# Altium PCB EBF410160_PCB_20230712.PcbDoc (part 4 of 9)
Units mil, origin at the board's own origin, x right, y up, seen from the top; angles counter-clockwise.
Board outline 5393.69 x 3858.26 mil, 6 copper layers (TOP, GND02, ART03, POW04, GND05, BOTTOM), stack 47.2 mil thick; 572 components, 434 nets, 2057 pads, 1177 vias.
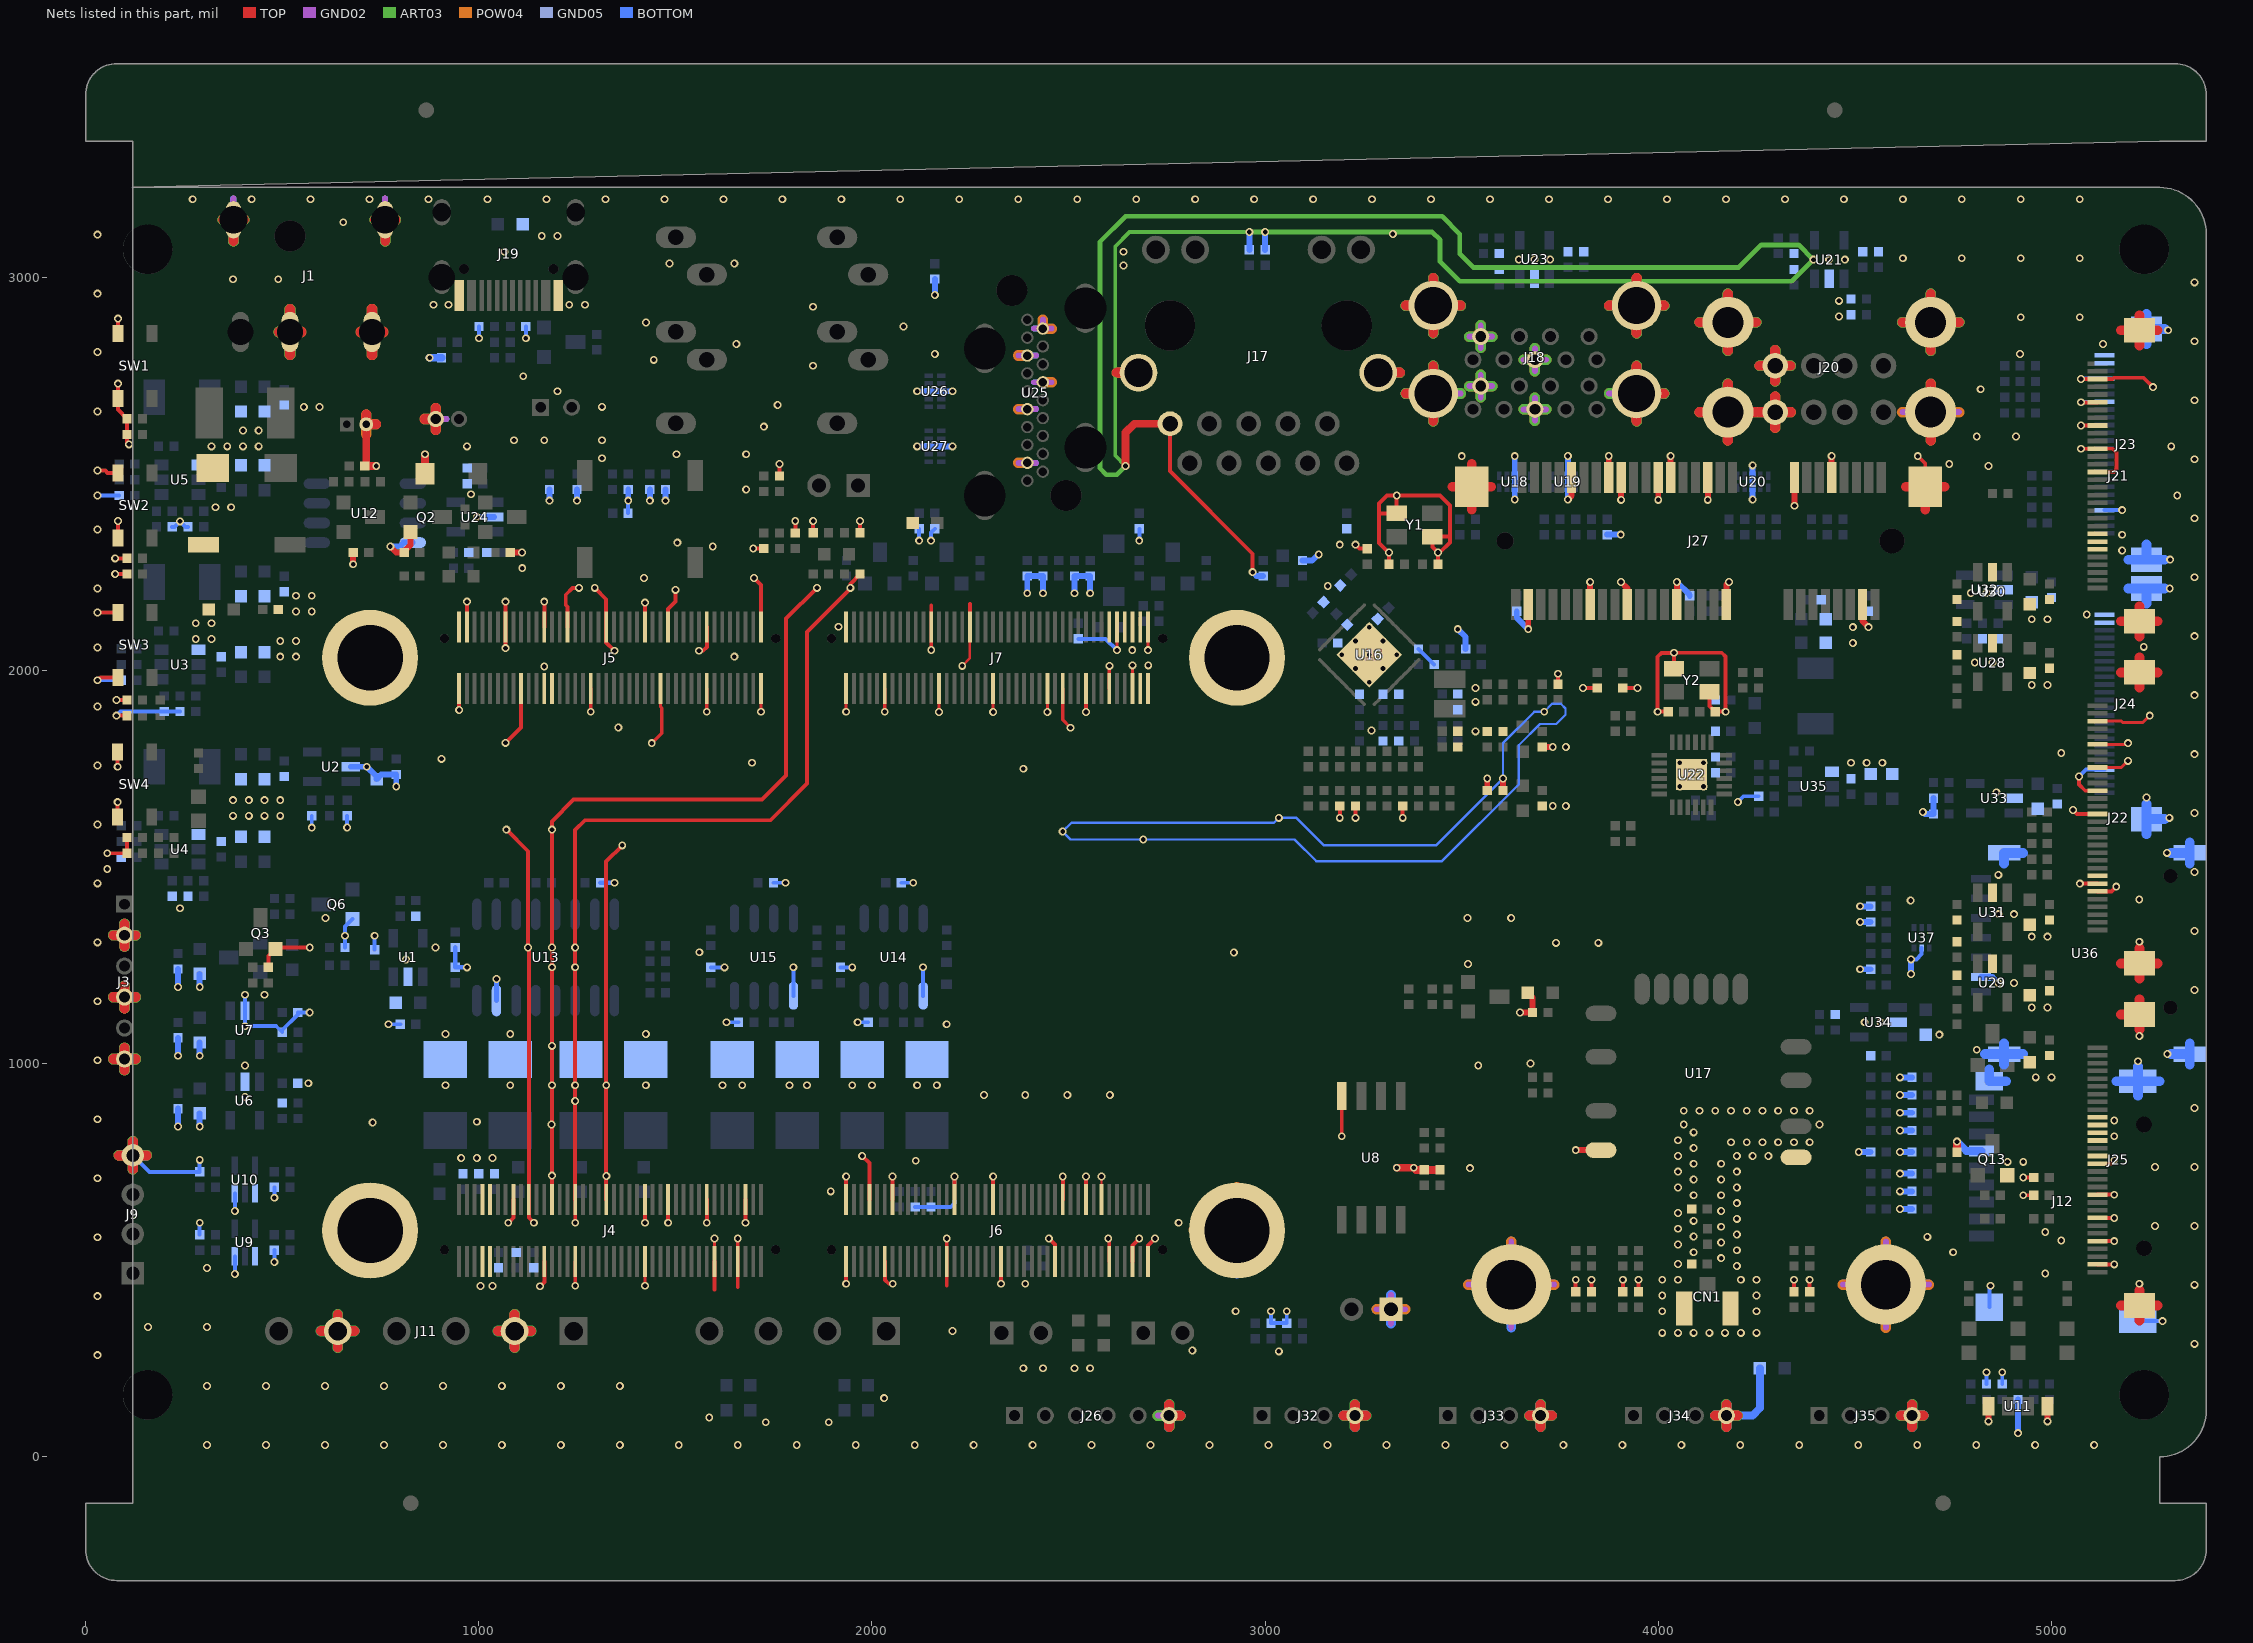
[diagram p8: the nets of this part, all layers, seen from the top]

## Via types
v1: diameter 20, hole 12, TOP to BOTTOM, 1177 vias

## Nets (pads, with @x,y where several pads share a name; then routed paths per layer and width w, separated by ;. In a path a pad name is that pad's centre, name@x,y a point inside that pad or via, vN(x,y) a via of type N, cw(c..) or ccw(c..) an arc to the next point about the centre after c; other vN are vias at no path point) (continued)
GND: C1.2 C2.2 C3.2 C4.2 C5.2 C6.2 C9.2 C10.2 C11.2 C12.2 C13.2 C14.2 C15.2 C16.2 C17.2 C18.1 C21.2 C22.2 C23.2 C24.2 C25.2 C26.2 C27.1 C30.2 C31.2 C32.2 C33.2 C34.2 C35.2 C36.2 C37.1 C39.2 C40.2 C41.2 C42.2 C43.2 C44.2 C45.2 C46.2 C47.2 C48.2 C49.2 C50.2 C51.2 C52.2 C53.2 C54.2 C55.2 C56.2 C57.2 C58.2 C59.2 C60.2 C61.2 C62.2 C63.2 C64.2 C65.2 C66.2 C67.2 C68.2 C71.2 C72.2 C73.2 C74.2 C75.2 C77.2 C78.2 C79.2 C80.2 C81.2 C82.2 C83.2 C84.2 C85.2 C86.2 C87.2 C88.2 C89.2 C90.2 C91.2 C92.2 C93.2 C94.2 C95.2 C96.2 C97.2 C98.2 C99.2 C100.2 C101.2 C102.2 C103.2 C105.2 C106.2 C108.2 C109.2 C110.2 C111.2 C114.2 C115.2 C116.2 C117.2 C118.1 C119.2 C120.2 C121.2 C122.2 C123.2 C124.2 C125.2 C126.2 C127.2 C128.2 C129.2 C130.2 C131.2 C132.2 C133.2 C134.2 C135.2 C136.2 C137.2 C138.2 C139.2 C140.2 C141.2 C142.2 C143.2 C144.2 C145.2 C148.2 C149.2 C150.2 C152.2 C153.2 C156.2 C157.2 C158.2 C159.2 C160.2 C161.2 C162.2 C163.2 C164.2 C167.2 C168.2 C169.2 C170.2 C171.2 C172.2 C173.2 C177.2 CN1.2 CN1.3 D1.2 D2.2 D3.1 D4.1 D5.1 D6.1 D7.1 D8.1 D10.1 D11.1 D12.1 D13.1 D14.1 D15.1 D16.1 D17.1 D18.1 D19.1 D20.1 D21.1 D24.1 D25.1 D26.1 D27.1 D30.1 D31.1 D33.1 D34.1 D35.1 D36.1 D37.1 D38.1 D39.1 D41.1 D42.1 D43.1 D44.1 D45.1 D46.1 D47.1 D48.1 D49.1 D50.1 D51.1 D52.1 D53.1 D54.1 J1.1 J1.2 J1.3 J1.5 J2.2 J3.2 J3.4 J3.6 J4.7 J4.8 J4.9 J4.10 J4.16 J4.20 J4.23 J4.26 J4.31 J4.32 J4.40 J4.49 J4.50 J4.56 J4.66 J4.67 J4.73 J4.76 J5.1 J5.2 J5.3 J5.13 J5.18 J5.23 J5.24 J5.26 J5.29 J5.36 J5.39 J5.49 J5.54 J5.55 J5.65 J5.66 J5.79 J5.80 J6.1 J6.2 J6.8 J6.11 J6.14 J6.27 J6.30 J6.40 J6.41 J6.55 J6.58 J6.64 J6.68 J6.69 J6.75 J6.79 J7.1 J7.2 J7.12 J7.23 J7.26 J7.33 J7.40 J7.54 J7.58 J7.64 J7.69 J7.70 J7.71 J7.73 J7.75 J7.76 J7.77 J7.78 J7.79 J7.80 J8.1 J9.4 J10.2 J11.2 J11.5 J12.6 J12.10 J12.11 J12.12 J12.13 J17.10 J17.15 J17.16 J18.4 J18.7 J18.13 J18.16 J18.19 J18.20 J18.21 J18.22 J19.A1 J19.A12 J19.B1 J19.B12 J20.4 J20.5 J20.6 J20.10 J20.11 J20.12 J21.6 J21.7 J21.8 J21.16 J21.19 J21.22 J21.25 J21.28 J21.31 J21.32 J22.6 J22.7 J22.8 J22.16 J22.19 J22.22 J22.25 J22.28 J22.31 J22.32 J23.4 J23.18 J23.21 J23.23 J23.24 J23.25 J23.26 J24.4 J24.23 J24.24 J24.25 J24.26 J25.2 J25.5 J25.8 J25.11 J25.15 J25.16 J25.18 J25.19 J25.20 J25.21 J25.31 J25.32 J26.6 J27.4 J27.9 J27.15 J27.18 J27.21 J27.26 J27.27 J27.29 J27.34 J27.35 J27.37 J27.40 J27.43 J27.50 J27.53 J27.54 J32.4 J33.4 J34.4 J35.4 L8.2 L9.2 Q2.2 Q3.2 Q6.2 Q13.2 R2.2 R5.2 R6.2 R8.2 R13.2 R15.2 R18.2 R21.2 R22.2 R25.2 R29.2 R31.2 R33.2 R35.2 R75.2 R76.2 R77.2 R78.2 R98.2 R103.2 R104.2 R105.2 R113.2 R114.2 R115.2 R116.2 R121.1 R143.2 R147.2 R150.2 R152.2 R154.2 R172.2 R173.2 R174.2 R175.2 R181.2 R187.2 R191.1 R194.2 R197.2 R203.2 R216.2 R217.2 R218.2 SS1.1 SS2.1 SS3.1 SS4.1 SS5.1 SS6.1 SW1.1 SW1.2 SW2.1 SW2.2 SW3.1 SW3.2 SW4.1 SW4.2 U1.2 U2.2 U3.1 U4.1 U5.1 U6.2 U7.2 U8.4 U9.1 U9.3 U10.1 U10.3 U11.1 U11.4 U12.4 U13.15 U14.5 U15.5 U16.41 U17.1 U17.5 U18.3 U18.8 U19.3 U19.8 U20.3 U20.8 U21.2 U22.25 U23.2 U24.2 U25.2 U25.5 U25.8 U25.11 U25.17 U26.3 U26.8 U27.3 U27.8 U28.2 U29.2 U30.2 U31.2 U32.2 U33.2 U34.2 U35.1 U36.5 U36.8 U36.9 U36.10 U36.11 U37.2 Y1.2 Y1.4 Y2.2 Y2.4 | length 67824.3
  TOP w6.16: v1(2229.53,2011.61) 2249.21,2031.3 J7.33@2249.21,2110.98 ; J6.68@2583.86,654.29 v1(2583.86,712.79)
  TOP w8: v1(1245.27,435) J4.31@1245.27,496.81 ; v1(1422.43,435) J4.49@1422.43,496.81 ; v1(1440,1815) 1465.28,1840.28 1465.28,1904.72 1461.8,1908.2 J5.54@1461.8,1953.5 ; v1(1579.91,1895) J5.66@1579.91,1953.5 ; J4.67@1599.6,496.81 v1(1599.6,555) ; J4.73@1658.65,496.81 v1(1658.65,555) ; v1(1717.71,1895) J5.80@1717.71,1953.5 ; v1(1934.25,1895) J7.2@1934.25,1953.5 ; v1(2032.68,1895) J7.12@2032.68,1953.5 ; v1(2150.79,2052) J7.23@2150.79,2110.98 ; v1(2170.47,1894.13) J7.26@2170.47,1953.5 ; v1(2308.27,1894.13) J7.40@2308.27,1953.5 ; v1(2446.06,1894.13) J7.54@2446.06,1953.5 ; J7.58@2485.43,1953.5 2485.43,1902.73 2485.12,1902.42 2485.12,1874.13 v1(2505.12,1854.13) ; v1(2623.23,2051.61) J7.71@2623.23,2110.98 ; J7.76@2662.6,1953.5 v1(2662.6,2012.87) ; v1(2701.97,2051.61) J7.79@2701.97,2110.98 ; J22.22@5117.47,1752.96 5177.96,1752.96 v1(5195,1770) ; J22.25@5117.47,1812.01 5192.01,1812.01 v1(5195,1815) ; J22.28@5117.47,1871.07 5177.65,1871.07 5181.12,1867.59 5232.59,1867.59 v1(5250,1885)
  TOP w10: v1(30,1975) 37.03,1982.03 SW3.1@82,1982.03 ; v1(30,2147.39) SW3.2@82,2147.39 ; v1(30,2508.34) 50,2508.34 55.95,2502.39 58.2,2502.39 ; v1(55,1535) C61.2@105.32,1535 D8.1@105.32,1575 ; 58.22,2502.37 SW2.2@82,2502.41 ; v1(75,2245) C58.2@105.32,2245 ; v1(75,2285) D4.1@105.32,2285 ; v1(78.52,1885) C60.2@105.32,1885 ; v1(78.52,1925) D7.1@105.32,1925 ; SW4.1@81.38,1627.59 v1(81.38,1665) ; v1(81.38,1755) SW4.2@81.38,1792.95 ; SW2.1@82,2337.05 v1(82,2380) ; v1(82,2729.42) SW1.1@82,2691.99 82,2663.32 D3.1@105.32,2640 C56.2@105.32,2600 105.32,2579.68 v1(110,2575) ; SW1.2@82,2857.35 v1(82,2894.78) ; R21.2@464.68,1245 464.68,1273.18 Q3.2@482.5,1291 486.5,1295 v1(570,1295) ; v1(949.99,1899.13) J5.2@949.99,1953.5 ; J5.3@969.68,2110.98 v1(969.68,2175) ; v1(1068.1,1815.7) 1107.47,1855.07 J5.18@1107.47,1953.5 ; v1(1068.1,2056.61) J5.13@1068.1,2110.98 v1(1068.1,2175) ; v1(1070,1595) 1125,1540 v1(1125,1295) 1127.16,1292.84 J4.20@1127.16,654.29 1127.16,607.84 v1(1140,595) ; v1(1075,595) 1087.79,607.79 J4.16@1087.79,654.29 ; v1(1155.89,433.62) 1166.53,444.26 J4.23@1166.53,496.81 ; J5.23@1166.53,2110.98 v1(1166.53,2175) ; J4.26@1186.21,654.29 v1(1186.21,715) v1(1186.21,945) v1(1186.21,1045) v1(1186.21,1245) v1(1186.21,1295) v1(1186.21,1595) 1186.21,1616.21 1241.32,1671.32 1720.16,1671.32 1781.56,1732.72 1781.56,2131.56 v1(1860,2210) ; J5.29@1225.58,2110.98 1225.58,2161.87 1221.11,2166.34 1221.11,2192.4 1238.71,2210 v1(1255,2210) ; v1(1245.27,595) J4.32@1245.27,654.29 1245,654.56 v1(1245,905) v1(1245,944.95) v1(1245,944.95) v1(1244.95,1245) v1(1244.95,1295) 1244.95,1593.79 1270.08,1618.92 1741.87,1618.92 1835,1712.06 1835,2098.2 1945,2208.2 v1(1945,2210) 1945,2220.32 R217.2@1969.68,2245 ; v1(1284.64,1895) J5.36@1284.64,1953.5 ; v1(1295,2210) 1324.01,2180.99 J5.39@1324.01,2110.98 1324.01,2070.82 1344.83,2050 v1(1345,2050) ; J4.40@1324.01,654.29 v1@1324.01,714.01 ; v1(1324.32,714.01) v1@1324.01,714.01 ; v1(1365,1555) 1324.01,1514.01 v1@1324.01,714.01 ; v1(1422.43,595) J4.50@1422.43,654.29 ; J5.49@1422.43,2110.98 v1(1422.43,2172.43) ; v1(1481.49,595) J4.56@1481.49,654.29 ; J5.55@1481.49,2110.98 1481.49,2156.49 1500,2175 v1(1500,2205) ; v1(1560,2050) 1569.91,2050 1579.91,2060 J5.65@1579.91,2110.98 ; v1(1579.91,595) J4.66@1579.91,654.29 ; 1599.6,425.4 J4.67@1599.6,496.81 ; 1658.65,431.35 J4.73@1658.65,496.81 ; v1(1678.34,595) J4.76@1678.34,654.29 ; v1(1698.2,2310.32) C172.2@1725,2310.32 ; v1(1700,2235) 1717.71,2217.29 J5.79@1717.71,2110.98 ; C177.2@1765,2494.68 v1(1765,2525) ; C171.2@1805,2349.68 v1(1805,2380) ; D41.1@1850.32,2350 v1(1850.32,2380.32) ; v1(1934.25,440) J6.1@1934.25,496.81 ; J6.2@1934.25,654.29 v1(1934.25,713) ; D44.1@1969.68,2350 v1(1969.68,2380) ; v1(1975,765) 1993.31,746.69 J6.8@1993.31,654.29 ; J6.11@2032.68,496.81 2032.68,450 2042.68,440 v1(2052.99,440) ; J6.14@2052.36,654.29 v1(2052.36,712.79) ; J7.23@2150.79,2110.98 2150.79,2164.94 ; 2190.16,434.84 J6.27@2190.16,496.81 v1(2190.16,555.31) ; J6.30@2209.84,654.29 v1(2209.84,712.79) ; J7.33@2249.21,2110.98 2249.21,2168.76 ; J6.40@2308.27,654.29 v1(2308.27,712.79) ; v1(2327.95,440) J6.41@2327.95,496.81 ; v1(2450,555) 2465.75,539.25 J6.55@2465.75,496.81 ; J6.58@2485.43,654.29 v1(2485.43,712.79) ; J6.64@2544.49,654.29 v1(2544.49,712.79) ; v1(2544.49,1894.13) J7.64@2544.49,1953.5 ; v1(2600.92,555) 2603.54,552.38 J6.69@2603.54,496.81 ; J7.70@2603.54,1953.5 2603.54,2010.98 v1(2604.17,2011.61) ; J6.75@2662.6,496.81 2662.6,537.6 v1(2680,555) ; J6.79@2701.97,496.81 2701.97,536.97 v1(2720,555) ; J17.10@2758.13,2627.52 2758.13,2506.87 2968.2,2296.8 v1(2968.2,2250) ; v1(3190,1625) R104.2@3190,1655.32 ; v1(3195,815) U8.4@3195,917.48 ; v1(3230,1625) R103.2@3230,1655.32 ; v1(3230,2320) 3240.32,2309.68 R98.2@3260,2309.68 ; C81.2@3315.32,2270 v1(3315.32,2300) 3314.36,2300 3290,2324.36 3290,2399 ; v1(3350,1625) R105.2@3350,1655.32 ; C82.2@3439.68,2270 v1(3439.68,2300) ; R113.2@3745,1964.68 v1(3745,1991.48) ; D48.1@3790,419.68 v1(3790,450) ; v1(3808.66,1955.32) D39.1@3845,1955.32 ; D47.1@3830,419.68 v1(3830,450) ; D52.1@3910,419.68 v1(3910,450) ; D38.1@3910,1955.32 v1(3947.03,1955.32) ; D51.1@3950,419.68 v1(3950,450) ; C118.1@4025.32,1895 v1(3998.52,1895) 3998.52,2034.72 4008.52,2044.72 v1@4039.72,2044.72 ; Y2.2@4039.72,2004.53 v1@4039.72,2044.72 ; Y2.4@4130.28,1945.47 4130.28,1909.4 C117.2@4144.68,1895 v1(4171.48,1895) 4171.48,2035 4161.48,2045 v1(4040,2045) v1@4039.72,2044.72 ; D54.1@4345,419.68 v1(4345,450) ; D53.1@4385,419.68 v1(4385,450) ; v1(4660,2545) 4679.19,2525.81 J27.54@4679.19,2467.26 ; v1(4928.52,665) R191.1@4955.32,665 ; v1(4928.52,710) C150.2@4955.32,710 ; v1(5055,1645) 5065.15,1634.85 J22.16@5117.47,1634.85 ; v1(5070,1730) 5070,1710 5086.1,1693.9 J22.19@5117.47,1693.9 ; v1(5072.32,1457.68) J22.7@5117.47,1457.68 ; v1(5075,2563.9) J21.19@5117.47,2563.9 5155.92,2563.9 5165.92,2553.9 5165.92,2511.92 5158.85,2504.85 J21.16@5117.47,2504.85 ; v1(5075,2622.96) J21.22@5117.47,2622.96 ; v1(5075,2682.01) J21.25@5117.47,2682.01 ; v1(5075,2741.07) J21.28@5117.47,2741.07 5156.07,2741.07 5159.38,2744.38 5234.64,2744.38 v1(5258.5,2720.52) ; J25.2@5117.47,489.26 v1(5160,489.26) ; J25.5@5117.47,548.31 v1(5160,548.31) ; J25.8@5117.47,607.37 v1(5160,607.37) ; J25.11@5117.47,666.42 v1(5160,666.42) ; J25.15@5117.47,745.16 5151.16,745.16 v1(5160,754) ; J22.6@5117.47,1438 5153,1438 v1(5165,1450) ; 3290,2399 3290,2425 3310,2445 v1(3334.72,2445) ; 3290,2399 3290.53,2399.53 Y1.4@3334.72,2399.53 v1(3334.72,2445) ; v1(3334.72,2445) 3445,2445 3470,2420 3470,2340 ; v1(3439.68,2300) 3425.28,2314.4 Y1.2@3425.28,2340.47 3469.53,2340.47 3470,2340 ; v1(3439.68,2300) 3444.22,2300 3470,2325.78 3470,2340
  TOP w15: v1(680.32,2270) C65.2@680.32,2300 ; v1(775,2315) 790,2300 R18.2@810.32,2300 810.32,2303.33 826.5,2319.51 Q2.2@826.5,2352.5 ; C30.2@1079.68,2300 v1(1110,2300) ; C102.2@3565,1694.68 v1(3565,1725) ; C101.2@3605,1694.68 v1(3605,1725) ; v1(3648.52,1130) C109.2@3680.32,1130 3680.32,1168.18 C108.2@3668.5,1180 ; v1(3669.34,2105) J27.50@3669.34,2168.04 ; C88.2@3705,1805.32 v1(3731.8,1805.32) ; v1(3770,2435) 3779.58,2444.58 J27.43@3779.58,2490.88 ; v1(3790,779.84) U17.5@3854.39,779.84 ; J27.40@3826.82,2168.04 v1(3826.82,2225) ; J27.37@3874.07,2490.88 v1(3874.07,2545.25) ; v1(3905,2225) 3921.31,2208.69 J27.34@3921.31,2168.04 ; v1(3905.57,2433.92) J27.35@3905.57,2490.88 ; v1(4000.05,2433.92) J27.29@4000.05,2490.88 ; J27.27@4031.55,2490.88 v1(4031.55,2545.25) ; J27.26@4047.3,2168.04 v1(4047.3,2225) ; v1(4126.04,2433.92) J27.21@4126.04,2490.88 ; J27.18@4173.28,2168.04 4173.28,2218.28 v1(4180,2225) ; v1(4346.51,2418.78) J27.15@4346.51,2490.88 ; J27.9@4441,2490.88 v1(4441,2545.25) ; J27.4@4519.74,2168.04 4519.74,2125.26 v1(4535,2110) ; v1(4840,90) U11.1@4840,128.74 ; v1(4990,90) U11.4@4990,128.74
  TOP w20: J10.2@713.59,2625.98 713.59,2523.91 D10.1@709.68,2520 v1(739,2520) ; D2.2@863.07,2500 v1(863.07,2550) ; v1(2645,2520) 2645,2605 2667.52,2627.52 J17.10@2758.13,2627.52 ; v1(3335,735) v1(3378.2,735) 3383.52,729.68 C55.2@3405,729.68 C54.2@3445,729.68 ; R197.2@4760,774.68 v1(4760,801.48)
  TOP w25: 70.08,1011.58 J3.6@98.74,1011.58 ; 70.08,1169.06 J3.4@98.74,1169.06 ; 70.08,1326.54 J3.2@98.74,1326.54 ; 84.45,766.54 J9.4@120,766.54 ; 98.74,982.92 J3.6@98.74,1011.58 ; 98.74,1040.23 J3.6@98.74,1011.58 ; 98.74,1140.4 J3.4@98.74,1169.06 ; 98.74,1197.71 J3.4@98.74,1169.06 ; 98.74,1297.88 J3.2@98.74,1326.54 ; 98.74,1355.19 J3.2@98.74,1326.54 ; 120,731 J9.4@120,766.54 ; 120,802.09 J9.4@120,766.54 ; 127.4,1011.58 J3.6@98.74,1011.58 ; 127.4,1169.06 J3.4@98.74,1169.06 ; 127.4,1326.54 J3.2@98.74,1326.54 ; 155.55,766.54 J9.4@120,766.54 ; 349.3,3146.28 J1.1@376,3146.28 ; 376,3092.03 J1.1@376,3146.28 ; 402.7,3146.28 J1.1@376,3146.28 ; 491.05,2860.78 J1.2@519.7,2860.78 ; 519.7,2802.57 J1.2@519.7,2860.78 ; 519.7,2918.98 J1.2@519.7,2860.78 ; 548.35,2860.78 J1.2@519.7,2860.78 ; 598.71,319.64 J11.5@641.14,319.64 ; 641.14,277.21 J11.5@641.14,319.64 ; 641.14,362.08 J11.5@641.14,319.64 ; 683.58,319.64 J11.5@641.14,319.64 ; 699.65,2860.78 J1.3@728.3,2860.78 ; 713.59,2650.7 J10.2@713.59,2625.98 738.31,2625.98 ; 728.3,2802.57 J1.3@728.3,2860.78 ; 728.3,2918.98 J1.3@728.3,2860.78 ; 735.1,3146.28 J1.5@761.8,3146.28 ; 756.96,2860.78 J1.3@728.3,2860.78 ; 761.8,3092.03 J1.5@761.8,3146.28 ; 788.51,3146.28 J1.5@761.8,3146.28 ; 862.8,2639.41 J2.2@890.47,2639.41 ; 890.47,2611.73 J2.2@890.47,2639.41 ; 890.47,2667.08 J2.2@890.47,2639.41 ; 1048.7,319.64 J11.2@1091.14,319.64 ; 1091.14,277.21 J11.2@1091.14,319.64 ; 1091.14,362.08 J11.2@1091.14,319.64 ; 1133.58,319.64 J11.2@1091.14,319.64 ; 2623.17,2757.44 J17.16@2678.01,2757.44 ; 2755.9,75.83 J26.6@2755.9,104.49 ; 2755.9,133.14 J26.6@2755.9,104.49 ; 2784.56,104.49 J26.6@2755.9,104.49 ; 3199.68,104.49 J32.4@3228.34,104.49 ; 3228.34,75.83 J32.4@3228.34,104.49 ; 3228.34,133.14 J32.4@3228.34,104.49 ; 3257,104.49 J32.4@3228.34,104.49 ; J17.15@3287.85,2757.44 3342.69,2757.44 ; 3357.63,2704.29 J18.20@3427.62,2704.29 ; 3357.63,2927.91 J18.19@3427.62,2927.91 ; 3427.62,2634.3 J18.20@3427.62,2704.29 ; 3427.62,2774.28 J18.20@3427.62,2704.29 ; 3427.62,2857.92 J18.19@3427.62,2927.91 ; 3427.62,2997.9 J18.19@3427.62,2927.91 ; 3476.32,2467.26 J27.53@3525.64,2467.26 ; 3497.61,2927.91 J18.19@3427.62,2927.91 ; 3525.64,2409.07 J27.53@3525.64,2467.26 ; 3525.64,2525.44 J27.53@3525.64,2467.26 ; 3574.97,2467.26 J27.53@3525.64,2467.26 ; 3672.12,104.49 J33.4@3700.78,104.49 ; 3700.78,75.83 J33.4@3700.78,104.49 ; 3700.78,133.14 J33.4@3700.78,104.49 ; 3729.44,104.49 J33.4@3700.78,104.49 ; 3874.96,2927.91 J18.22@3944.95,2927.91 ; 3944.95,2634.3 J18.21@3944.95,2704.29 ; 3944.95,2774.28 J18.21@3944.95,2704.29 ; 3944.95,2857.92 J18.22@3944.95,2927.91 ; 3944.95,2997.9 J18.22@3944.95,2927.91 ; 4014.94,2704.29 J18.21@3944.95,2704.29 ; 4014.94,2927.91 J18.22@3944.95,2927.91 ; 4105.27,2657.04 J20.5@4177.23,2657.04 ; 4105.27,2885.39 J20.11@4177.23,2885.39 ; 4144.56,104.49 J34.4@4173.22,104.49 ; 4173.22,75.83 J34.4@4173.22,104.49 ; 4173.22,133.14 J34.4@4173.22,104.49 ; 4177.23,2585.08 J20.5@4177.23,2657.04 ; 4177.23,2729 J20.5@4177.23,2657.04 ; 4177.23,2813.43 J20.11@4177.23,2885.39 ; 4177.23,2957.35 J20.11@4177.23,2885.39 ; 4201.88,104.49 J34.4@4173.22,104.49 ; 4249.19,2657.04 J20.5@4177.23,2657.04 ; 4249.19,2885.39 J20.11@4177.23,2885.39 ; 4257.8,2657.04 J20.4@4297.3,2657.04 ; 4257.8,2775.15 J20.10@4297.3,2775.15 ; 4297.3,2617.54 J20.4@4297.3,2657.04 ; 4297.3,2696.54 J20.4@4297.3,2657.04 ; 4297.3,2735.65 J20.10@4297.3,2775.15 ; 4297.3,2814.65 J20.10@4297.3,2775.15 ; 4336.8,2657.04 J20.4@4297.3,2657.04 ; 4336.8,2775.15 J20.10@4297.3,2775.15 ; 4617,104.49 J35.4@4645.66,104.49 ; 4621.01,2885.39 J20.12@4692.97,2885.39 ; 4629.86,2467.26 J27.54@4679.19,2467.26 ; 4645.66,75.83 J35.4@4645.66,104.49 ; 4645.66,133.14 J35.4@4645.66,104.49 ; 4674.32,104.49 J35.4@4645.66,104.49 ; 4679.19,2409.07 J27.54@4679.19,2467.26 ; 4692.97,2585.08 J20.6@4692.97,2657.04 4692.97,2729 ; 4692.97,2813.43 J20.12@4692.97,2885.39 ; 4692.97,2957.35 J20.12@4692.97,2885.39 ; 4728.51,2467.26 J27.54@4679.19,2467.26 ; 4764.93,2885.39 J20.12@4692.97,2885.39 ; 5177.4,384.92 J25.32@5223.77,384.92 ; 5177.4,1125.08 J25.31@5223.77,1125.08 ; 5177.4,1254.92 J22.32@5223.77,1254.92 ; 5177.4,1995.08 J22.31@5223.77,1995.08 ; 5177.4,2124.92 J21.32@5223.77,2124.92 ; 5177.4,2865.08 J21.31@5223.77,2865.08 ; 5223.77,346.42 J25.32@5223.77,384.92 ; 5223.77,423.41 J25.32@5223.77,384.92 ; 5223.77,1086.58 J25.31@5223.77,1125.08 ; 5223.77,1163.57 J25.31@5223.77,1125.08 ; 5223.77,1216.42 J22.32@5223.77,1254.92 ; 5223.77,1293.41 J22.32@5223.77,1254.92 ; 5223.77,1956.58 J22.31@5223.77,1995.08 ; 5223.77,2033.57 J22.31@5223.77,1995.08 ; 5223.77,2086.42 J21.32@5223.77,2124.92 ; 5223.77,2163.41 J21.32@5223.77,2124.92 ; 5223.77,2826.58 J21.31@5223.77,2865.08 ; 5223.77,2903.57 J21.31@5223.77,2865.08 ; 5270.14,384.92 J25.32@5223.77,384.92 ; 5270.14,1254.92 J22.32@5223.77,1254.92 ; 5270.14,1995.08 J22.31@5223.77,1995.08 ; 5270.14,2124.92 J21.32@5223.77,2124.92 ; 5270.14,2865.08 J21.31@5223.77,2865.08
  GND02 w15: 70.08,1011.58 J3.6@98.74,1011.58 ; 70.08,1169.06 J3.4@98.74,1169.06 ; 70.08,1326.54 J3.2@98.74,1326.54 ; 84.45,766.54 J9.4@120,766.54 ; 98.74,982.92 J3.6@98.74,1011.58 ; 98.74,1040.23 J3.6@98.74,1011.58 ; 98.74,1140.4 J3.4@98.74,1169.06 ; 98.74,1197.71 J3.4@98.74,1169.06 ; 98.74,1297.88 J3.2@98.74,1326.54 ; 98.74,1355.19 J3.2@98.74,1326.54 ; 120,731 J9.4@120,766.54 ; 120,802.09 J9.4@120,766.54 ; 127.4,1011.58 J3.6@98.74,1011.58 ; 127.4,1169.06 J3.4@98.74,1169.06 ; 127.4,1326.54 J3.2@98.74,1326.54 ; 155.55,766.54 J9.4@120,766.54 ; 349.3,3146.28 J1.1@376,3146.28 ; 376,3092.03 J1.1@376,3146.28 ; 376,3200.53 J1.1@376,3146.28 ; 402.7,3146.28 J1.1@376,3146.28 ; 491.05,2860.78 J1.2@519.7,2860.78 ; 519.7,2802.57 J1.2@519.7,2860.78 ; 519.7,2918.98 J1.2@519.7,2860.78 ; 548.35,2860.78 J1.2@519.7,2860.78 ; 598.71,319.64 J11.5@641.14,319.64 ; 614.26,575.55 SS1.1@723.62,575.55 ; 614.26,2032.24 SS3.1@723.62,2032.24 ; 641.14,277.21 J11.5@641.14,319.64 ; 641.14,362.08 J11.5@641.14,319.64 ; 683.58,319.64 J11.5@641.14,319.64 ; 699.65,2860.78 J1.3@728.3,2860.78 ; 713.59,2601.26 J10.2@713.59,2625.98 ; 713.59,2650.7 J10.2@713.59,2625.98 ; 723.62,466.19 SS1.1@723.62,575.55 ; 723.62,684.91 SS1.1@723.62,575.55 ; 723.62,1922.88 SS3.1@723.62,2032.24 ; 723.62,2141.6 SS3.1@723.62,2032.24 ; 728.3,2802.57 J1.3@728.3,2860.78 ; 728.3,2918.98 J1.3@728.3,2860.78 ; 735.1,3146.28 J1.5@761.8,3146.28 ; 738.31,2625.98 J10.2@713.59,2625.98 ; 756.96,2860.78 J1.3@728.3,2860.78 ; 761.8,3092.03 J1.5@761.8,3146.28 ; 761.8,3200.53 J1.5@761.8,3146.28 ; 788.51,3146.28 J1.5@761.8,3146.28 ; 832.98,575.55 SS1.1@723.62,575.55 ; 832.98,2032.24 SS3.1@723.62,2032.24 ; 862.8,2639.41 J2.2@890.47,2639.41 ; 890.47,2611.73 J2.2@890.47,2639.41 ; 890.47,2667.08 J2.2@890.47,2639.41 ; 918.14,2639.41 J2.2@890.47,2639.41 ; 1048.7,319.64 J11.2@1091.14,319.64 ; 1091.14,277.21 J11.2@1091.14,319.64 ; 1091.14,362.08 J11.2@1091.14,319.64 ; 1133.58,319.64 J11.2@1091.14,319.64 ; 2372.42,2528.08 U25.17@2395.17,2528.08 2417.92,2528.08 ; 2372.42,2664.49 U25.11@2395.17,2664.49 2417.92,2664.49 ; 2372.42,2800.91 U25.5@2395.17,2800.91 2417.92,2800.91 ; 2411.79,2732.92 U25.8@2434.54,2732.92 2457.29,2732.92 ; 2411.79,2869.46 U25.2@2434.54,2869.46 ; 2434.54,2892.21 U25.2@2434.54,2869.46 ; 2457.29,2869.46 U25.2@2434.54,2869.46 ; 2727.24,104.49 J26.6@2755.9,104.49 ; 2755.9,75.83 J26.6@2755.9,104.49 ; 2755.9,133.14 J26.6@2755.9,104.49 ; 2784.56,104.49 J26.6@2755.9,104.49 ; 2818.98,575.55 SS2.1@2928.34,575.55 ; 2818.98,2032.24 SS4.1@2928.34,2032.24 ; 2928.34,466.19 SS2.1@2928.34,575.55 ; 2928.34,684.91 SS2.1@2928.34,575.55 ; 2928.34,1922.88 SS4.1@2928.34,2032.24 ; 2928.34,2141.6 SS4.1@2928.34,2032.24 ; 3037.7,575.55 SS2.1@2928.34,575.55 ; 3037.7,2032.24 SS4.1@2928.34,2032.24 ; 3199.68,104.49 J32.4@3228.34,104.49 ; 3228.34,75.83 J32.4@3228.34,104.49 ; 3228.34,133.14 J32.4@3228.34,104.49 ; 3257,104.49 J32.4@3228.34,104.49 ; 3283.47,375 J8.1@3320,375 ; 3320,338.47 J8.1@3320,375 ; 3320,411.53 J8.1@3320,375 ; 3356.53,375 J8.1@3320,375 ; 3357.63,2704.29 J18.20@3427.62,2704.29 ; 3357.63,2927.91 J18.19@3427.62,2927.91 ; 3427.62,2634.3 J18.20@3427.62,2704.29 ; 3427.62,2774.28 J18.20@3427.62,2704.29 ; 3427.62,2857.92 J18.19@3427.62,2927.91 ; 3427.62,2997.9 J18.19@3427.62,2927.91 ; 3497.61,2704.29 J18.20@3427.62,2704.29 ; 3497.61,2927.91 J18.19@3427.62,2927.91 ; 3516.67,437.78 SS5.1@3626.03,437.78 ; 3519.83,2723.19 J18.13@3548.49,2723.19 ; 3519.83,2849.17 J18.4@3548.49,2849.17 ; 3548.49,2694.53 J18.13@3548.49,2723.19 ; 3548.49,2751.85 J18.13@3548.49,2723.19 ; 3548.49,2820.51 J18.4@3548.49,2849.17 ; 3548.49,2877.83 J18.4@3548.49,2849.17 ; 3577.15,2723.19 J18.13@3548.49,2723.19 ; 3577.15,2849.17 J18.4@3548.49,2849.17 ; 3626.03,328.42 SS5.1@3626.03,437.78 ; 3626.03,547.14 SS5.1@3626.03,437.78 ; 3657.62,2664.13 J18.16@3686.28,2664.13 ; 3657.62,2790.12 J18.7@3686.28,2790.12 ; 3672.12,104.49 J33.4@3700.78,104.49 ; 3686.28,2635.47 J18.16@3686.28,2664.13 ; 3686.28,2692.79 J18.16@3686.28,2664.13 ; 3686.28,2761.46 J18.7@3686.28,2790.12 ; 3686.28,2818.78 J18.7@3686.28,2790.12 ; 3700.78,75.83 J33.4@3700.78,104.49 ; 3700.78,133.14 J33.4@3700.78,104.49 ; 3714.94,2664.13 J18.16@3686.28,2664.13 ; 3714.94,2790.12 J18.7@3686.28,2790.12 ; 3729.44,104.49 J33.4@3700.78,104.49 ; 3735.39,437.78 SS5.1@3626.03,437.78 ; 3874.96,2704.29 J18.21@3944.95,2704.29 ; 3874.96,2927.91 J18.22@3944.95,2927.91 ; 3944.95,2634.3 J18.21@3944.95,2704.29 ; 3944.95,2774.28 J18.21@3944.95,2704.29 ; 3944.95,2857.92 J18.22@3944.95,2927.91 ; 3944.95,2997.9 J18.22@3944.95,2927.91 ; 4014.94,2704.29 J18.21@3944.95,2704.29 ; 4014.94,2927.91 J18.22@3944.95,2927.91 ; 4105.27,2657.04 J20.5@4177.23,2657.04 ; 4105.27,2885.39 J20.11@4177.23,2885.39 ; 4144.56,104.49 J34.4@4173.22,104.49 ; 4173.22,75.83 J34.4@4173.22,104.49 ; 4173.22,133.14 J34.4@4173.22,104.49 ; 4177.23,2585.08 J20.5@4177.23,2657.04 ; 4177.23,2729 J20.5@4177.23,2657.04 ; 4177.23,2813.43 J20.11@4177.23,2885.39 ; 4177.23,2957.35 J20.11@4177.23,2885.39 ; 4201.88,104.49 J34.4@4173.22,104.49 ; 4249.19,2657.04 J20.5@4177.23,2657.04 ; 4249.19,2885.39 J20.11@4177.23,2885.39 ; 4257.8,2657.04 J20.4@4297.3,2657.04 ; 4257.8,2775.15 J20.10@4297.3,2775.15 ; 4297.3,2617.54 J20.4@4297.3,2657.04 ; 4297.3,2696.54 J20.4@4297.3,2657.04 ; 4297.3,2735.65 J20.10@4297.3,2775.15 ; 4297.3,2814.65 J20.10@4297.3,2775.15 ; 4336.8,2657.04 J20.4@4297.3,2657.04 ; 4336.8,2775.15 J20.10@4297.3,2775.15 ; 4469.43,437.78 SS6.1@4578.79,437.78 ; 4578.79,328.42 SS6.1@4578.79,437.78 ; 4578.79,547.14 SS6.1@4578.79,437.78 ; 4617,104.49 J35.4@4645.66,104.49 ; 4621.01,2657.04 J20.6@4692.97,2657.04 ; 4621.01,2885.39 J20.12@4692.97,2885.39 ; 4645.66,75.83 J35.4@4645.66,104.49 ; 4645.66,133.14 J35.4@4645.66,104.49 ; 4674.32,104.49 J35.4@4645.66,104.49 ; 4688.15,437.78 SS6.1@4578.79,437.78 ; 4692.97,2585.08 J20.6@4692.97,2657.04 ; 4692.97,2729 J20.6@4692.97,2657.04 ; 4692.97,2813.43 J20.12@4692.97,2885.39 ; 4692.97,2957.35 J20.12@4692.97,2885.39 ; 4764.93,2657.04 J20.6@4692.97,2657.04 ; 4764.93,2885.39 J20.12@4692.97,2885.39
  GND02 w20: 2623.17,2757.44 J17.16@2678.01,2757.44 ; J17.15@3287.85,2757.44 3342.69,2757.44
  ART03 w10: v1(2645,2520) 2618.8,2546.2 2618.8,3078.8 2655,3115 v1(2960,3115)
  ART03 w12: v1(2645,2520) 2623,2498 2595.89,2498 2580,2513.89 2580,3090 2645,3155 3450,3155 3495,3110 3495,3059.45 3529.45,3025 4205,3025 4262.32,3082.32 4357.05,3082.32 v1(4394.61,3044.76) 4339.85,2990 3495,2990 3445,3040 3445,3095 3425,3115 v1(3000,3115) v1(2960,3115)
  ART03 w27: 70.08,1011.58 J3.6@98.74,1011.58 ; 70.08,1169.06 J3.4@98.74,1169.06 ; 70.08,1326.54 J3.2@98.74,1326.54 ; 84.45,766.54 J9.4@120,766.54 ; 98.74,982.92 J3.6@98.74,1011.58 ; 98.74,1040.23 J3.6@98.74,1011.58 ; 98.74,1140.4 J3.4@98.74,1169.06 ; 98.74,1197.71 J3.4@98.74,1169.06 ; 98.74,1297.88 J3.2@98.74,1326.54 ; 98.74,1355.19 J3.2@98.74,1326.54 ; 120,731 J9.4@120,766.54 ; 120,802.09 J9.4@120,766.54 ; 127.4,1011.58 J3.6@98.74,1011.58 ; 127.4,1169.06 J3.4@98.74,1169.06 ; 127.4,1326.54 J3.2@98.74,1326.54 ; 155.55,766.54 J9.4@120,766.54 ; 349.3,3146.28 J1.1@376,3146.28 ; 376,3092.03 J1.1@376,3146.28 ; 402.7,3146.28 J1.1@376,3146.28 ; 491.05,2860.78 J1.2@519.7,2860.78 ; 519.7,2802.57 J1.2@519.7,2860.78 ; 519.7,2918.98 J1.2@519.7,2860.78 ; 598.71,319.64 J11.5@641.14,319.64 ; 641.14,277.21 J11.5@641.14,319.64 ; 641.14,362.08 J11.5@641.14,319.64 ; 683.58,319.64 J11.5@641.14,319.64 ; 735.1,3146.28 J1.5@761.8,3146.28 ; 761.8,3092.03 J1.5@761.8,3146.28 ; 788.51,3146.28 J1.5@761.8,3146.28 ; 1048.7,319.64 J11.2@1091.14,319.64 ; 1091.14,277.21 J11.2@1091.14,319.64 ; 1091.14,362.08 J11.2@1091.14,319.64 ; 1133.58,319.64 J11.2@1091.14,319.64 ; 2727.24,104.49 J26.6@2755.9,104.49 ; 2755.9,75.83 J26.6@2755.9,104.49 ; 2755.9,133.14 J26.6@2755.9,104.49 ; 2784.56,104.49 J26.6@2755.9,104.49 ; 3199.68,104.49 J32.4@3228.34,104.49 ; 3228.34,75.83 J32.4@3228.34,104.49 ; 3228.34,133.14 J32.4@3228.34,104.49 ; 3257,104.49 J32.4@3228.34,104.49 ; J17.15@3287.85,2757.44 3342.69,2757.44 ; 3357.63,2704.29 J18.20@3427.62,2704.29 ; 3357.63,2927.91 J18.19@3427.62,2927.91 ; 3427.62,2634.3 J18.20@3427.62,2704.29 ; 3427.62,2774.28 J18.20@3427.62,2704.29 ; 3427.62,2857.92 J18.19@3427.62,2927.91 ; 3427.62,2997.9 J18.19@3427.62,2927.91 ; 3497.61,2704.29 J18.20@3427.62,2704.29 ; 3497.61,2927.91 J18.19@3427.62,2927.91 ; 3519.83,2723.19 J18.13@3548.49,2723.19 ; 3519.83,2849.17 J18.4@3548.49,2849.17 ; 3548.49,2694.53 J18.13@3548.49,2723.19 ; 3548.49,2751.85 J18.13@3548.49,2723.19 ; 3548.49,2820.51 J18.4@3548.49,2849.17 ; 3548.49,2877.83 J18.4@3548.49,2849.17 ; 3577.15,2723.19 J18.13@3548.49,2723.19 ; 3577.15,2849.17 J18.4@3548.49,2849.17 ; 3657.62,2664.13 J18.16@3686.28,2664.13 ; 3657.62,2790.12 J18.7@3686.28,2790.12 ; 3672.12,104.49 J33.4@3700.78,104.49 ; 3686.28,2635.47 J18.16@3686.28,2664.13 ; 3686.28,2692.79 J18.16@3686.28,2664.13 ; 3686.28,2761.46 J18.7@3686.28,2790.12 ; 3686.28,2818.78 J18.7@3686.28,2790.12 ; 3700.78,75.83 J33.4@3700.78,104.49 ; 3700.78,133.14 J33.4@3700.78,104.49 ; 3714.94,2664.13 J18.16@3686.28,2664.13 ; 3714.94,2790.12 J18.7@3686.28,2790.12 ; 3729.44,104.49 J33.4@3700.78,104.49 ; 3874.96,2704.29 J18.21@3944.95,2704.29 ; 3874.96,2927.91 J18.22@3944.95,2927.91 ; 3944.95,2634.3 J18.21@3944.95,2704.29 ; 3944.95,2774.28 J18.21@3944.95,2704.29 ; 3944.95,2857.92 J18.22@3944.95,2927.91 ; 4014.94,2704.29 J18.21@3944.95,2704.29 ; 4014.94,2927.91 J18.22@3944.95,2927.91 ; 4105.27,2885.39 J20.11@4177.23,2885.39 ; 4144.56,104.49 J34.4@4173.22,104.49 ; 4173.22,75.83 J34.4@4173.22,104.49 ; 4173.22,133.14 J34.4@4173.22,104.49 ; J20.5@4177.23,2657.04 4177.23,2729 ; 4177.23,2813.43 J20.11@4177.23,2885.39 ; 4177.23,2957.35 J20.11@4177.23,2885.39 ; 4201.88,104.49 J34.4@4173.22,104.49 ; 4249.19,2885.39 J20.11@4177.23,2885.39 ; 4257.8,2775.15 J20.10@4297.3,2775.15 ; 4297.3,2735.65 J20.10@4297.3,2775.15 ; 4297.3,2814.65 J20.10@4297.3,2775.15 ; 4336.8,2775.15 J20.10@4297.3,2775.15 ; 4617,104.49 J35.4@4645.66,104.49 ; 4621.01,2885.39 J20.12@4692.97,2885.39 ; 4645.66,75.83 J35.4@4645.66,104.49 ; 4645.66,133.14 J35.4@4645.66,104.49 ; 4674.32,104.49 J35.4@4645.66,104.49 ; 4692.97,2813.43 J20.12@4692.97,2885.39 ; 4692.97,2957.35 J20.12@4692.97,2885.39 ; 4764.93,2885.39 J20.12@4692.97,2885.39
  POW04 w27: 70.08,1011.58 J3.6@98.74,1011.58 ; 70.08,1169.06 J3.4@98.74,1169.06 ; 70.08,1326.54 J3.2@98.74,1326.54 ; 84.45,766.54 J9.4@120,766.54 ; 98.74,982.92 J3.6@98.74,1011.58 ; 98.74,1040.23 J3.6@98.74,1011.58 ; 98.74,1140.4 J3.4@98.74,1169.06 ; 98.74,1197.71 J3.4@98.74,1169.06 ; 98.74,1297.88 J3.2@98.74,1326.54 ; 98.74,1355.19 J3.2@98.74,1326.54 ; 120,731 J9.4@120,766.54 ; 120,802.09 J9.4@120,766.54 ; 127.4,1011.58 J3.6@98.74,1011.58 ; 127.4,1169.06 J3.4@98.74,1169.06 ; 127.4,1326.54 J3.2@98.74,1326.54 ; 155.55,766.54 J9.4@120,766.54 ; 349.3,3146.28 J1.1@376,3146.28 ; 376,3092.03 J1.1@376,3146.28 ; 402.7,3146.28 J1.1@376,3146.28 ; 491.05,2860.78 J1.2@519.7,2860.78 ; 519.7,2802.57 J1.2@519.7,2860.78 ; 519.7,2918.98 J1.2@519.7,2860.78 ; 548.35,2860.78 J1.2@519.7,2860.78 ; 699.65,2860.78 J1.3@728.3,2860.78 ; 713.59,2601.26 J10.2@713.59,2625.98 ; 713.59,2650.7 J10.2@713.59,2625.98 ; 728.3,2802.57 J1.3@728.3,2860.78 ; 728.3,2918.98 J1.3@728.3,2860.78 ; 735.1,3146.28 J1.5@761.8,3146.28 ; 738.31,2625.98 J10.2@713.59,2625.98 ; 756.96,2860.78 J1.3@728.3,2860.78 ; 761.8,3092.03 J1.5@761.8,3146.28 ; 788.51,3146.28 J1.5@761.8,3146.28 ; 862.8,2639.41 J2.2@890.47,2639.41 ; 890.47,2611.73 J2.2@890.47,2639.41 ; 890.47,2667.08 J2.2@890.47,2639.41 ; J11.2@1091.14,319.64 1091.14,362.08 ; 2372.42,2528.08 U25.17@2395.17,2528.08 ; 2372.42,2664.49 U25.11@2395.17,2664.49 ; 2372.42,2800.91 U25.5@2395.17,2800.91 ; U25.8@2434.54,2732.92 2457.29,2732.92 ; 2434.54,2892.21 U25.2@2434.54,2869.46 2457.29,2869.46 ; 2623.17,2757.44 J17.16@2678.01,2757.44 ; 2727.24,104.49 J26.6@2755.9,104.49 ; 2755.9,75.83 J26.6@2755.9,104.49 ; 2784.56,104.49 J26.6@2755.9,104.49 ; 2818.98,575.55 SS2.1@2928.34,575.55 ; 2928.34,684.91 SS2.1@2928.34,575.55 ; 3037.7,575.55 SS2.1@2928.34,575.55 ; 3283.47,375 J8.1@3320,375 3356.53,375 ; J17.15@3287.85,2757.44 3342.69,2757.44 ; 3357.63,2704.29 J18.20@3427.62,2704.29 ; 3357.63,2927.91 J18.19@3427.62,2927.91 ; 3427.62,2634.3 J18.20@3427.62,2704.29 ; 3427.62,2774.28 J18.20@3427.62,2704.29 ; 3427.62,2857.92 J18.19@3427.62,2927.91 ; 3427.62,2997.9 J18.19@3427.62,2927.91 ; 3497.61,2704.29 J18.20@3427.62,2704.29 ; 3497.61,2927.91 J18.19@3427.62,2927.91 ; 3516.67,437.78 SS5.1@3626.03,437.78 ; 3519.83,2723.19 J18.13@3548.49,2723.19 ; 3519.83,2849.17 J18.4@3548.49,2849.17 ; 3548.49,2694.53 J18.13@3548.49,2723.19 ; 3548.49,2751.85 J18.13@3548.49,2723.19 ; 3548.49,2820.51 J18.4@3548.49,2849.17 ; 3548.49,2877.83 J18.4@3548.49,2849.17 ; 3577.15,2723.19 J18.13@3548.49,2723.19 ; 3577.15,2849.17 J18.4@3548.49,2849.17 ; 3626.03,547.14 SS5.1@3626.03,437.78 ; 3657.62,2664.13 J18.16@3686.28,2664.13 ; 3657.62,2790.12 J18.7@3686.28,2790.12 ; 3686.28,2635.47 J18.16@3686.28,2664.13 ; 3686.28,2692.79 J18.16@3686.28,2664.13 ; 3686.28,2761.46 J18.7@3686.28,2790.12 ; 3686.28,2818.78 J18.7@3686.28,2790.12 ; 3714.94,2664.13 J18.16@3686.28,2664.13 ; 3714.94,2790.12 J18.7@3686.28,2790.12 ; 3735.39,437.78 SS5.1@3626.03,437.78 ; 3874.96,2704.29 J18.21@3944.95,2704.29 ; 3874.96,2927.91 J18.22@3944.95,2927.91 ; 3944.95,2634.3 J18.21@3944.95,2704.29 ; 3944.95,2774.28 J18.21@3944.95,2704.29 ; 3944.95,2857.92 J18.22@3944.95,2927.91 ; 3944.95,2997.9 J18.22@3944.95,2927.91 ; 4014.94,2704.29 J18.21@3944.95,2704.29 ; 4014.94,2927.91 J18.22@3944.95,2927.91 ; 4105.27,2657.04 J20.5@4177.23,2657.04 ; 4105.27,2885.39 J20.11@4177.23,2885.39 ; 4177.23,2585.08 J20.5@4177.23,2657.04 ; 4177.23,2729 J20.5@4177.23,2657.04 ; 4177.23,2813.43 J20.11@4177.23,2885.39 ; 4177.23,2957.35 J20.11@4177.23,2885.39 ; 4249.19,2657.04 J20.5@4177.23,2657.04 ; 4249.19,2885.39 J20.11@4177.23,2885.39 ; 4257.8,2657.04 J20.4@4297.3,2657.04 ; 4257.8,2775.15 J20.10@4297.3,2775.15 ; 4297.3,2617.54 J20.4@4297.3,2657.04 ; 4297.3,2696.54 J20.4@4297.3,2657.04 ; 4297.3,2735.65 J20.10@4297.3,2775.15 ; 4297.3,2814.65 J20.10@4297.3,2775.15 ; 4336.8,2657.04 J20.4@4297.3,2657.04 ; 4336.8,2775.15 J20.10@4297.3,2775.15 ; 4469.43,437.78 SS6.1@4578.79,437.78 ; 4578.79,328.42 SS6.1@4578.79,437.78 ; 4578.79,547.14 SS6.1@4578.79,437.78 ; 4621.01,2657.04 J20.6@4692.97,2657.04 ; 4621.01,2885.39 J20.12@4692.97,2885.39 ; 4688.15,437.78 SS6.1@4578.79,437.78 ; 4692.97,2585.08 J20.6@4692.97,2657.04 ; 4692.97,2729 J20.6@4692.97,2657.04 ; 4692.97,2813.43 J20.12@4692.97,2885.39 ; 4692.97,2957.35 J20.12@4692.97,2885.39 ; 4764.93,2657.04 J20.6@4692.97,2657.04 ; 4764.93,2885.39 J20.12@4692.97,2885.39
  GND05 w15: 70.08,1011.58 J3.6@98.74,1011.58 ; 70.08,1169.06 J3.4@98.74,1169.06 ; 70.08,1326.54 J3.2@98.74,1326.54 ; 84.45,766.54 J9.4@120,766.54 ; 98.74,982.92 J3.6@98.74,1011.58 ; 98.74,1040.23 J3.6@98.74,1011.58 ; 98.74,1140.4 J3.4@98.74,1169.06 ; 98.74,1197.71 J3.4@98.74,1169.06 ; 98.74,1297.88 J3.2@98.74,1326.54 ; 98.74,1355.19 J3.2@98.74,1326.54 ; 120,731 J9.4@120,766.54 ; 120,802.09 J9.4@120,766.54 ; 127.4,1011.58 J3.6@98.74,1011.58 ; 127.4,1169.06 J3.4@98.74,1169.06 ; 127.4,1326.54 J3.2@98.74,1326.54 ; 155.55,766.54 J9.4@120,766.54 ; 349.3,3146.28 J1.1@376,3146.28 ; 376,3092.03 J1.1@376,3146.28 ; 376,3200.53 J1.1@376,3146.28 ; 402.7,3146.28 J1.1@376,3146.28 ; 491.05,2860.78 J1.2@519.7,2860.78 ; 519.7,2802.57 J1.2@519.7,2860.78 ; 519.7,2918.98 J1.2@519.7,2860.78 ; 548.35,2860.78 J1.2@519.7,2860.78 ; 598.71,319.64 J11.5@641.14,319.64 ; 614.26,575.55 SS1.1@723.62,575.55 ; 614.26,2032.24 SS3.1@723.62,2032.24 ; 641.14,277.21 J11.5@641.14,319.64 ; 641.14,362.08 J11.5@641.14,319.64 ; 683.58,319.64 J11.5@641.14,319.64 ; 699.65,2860.78 J1.3@728.3,2860.78 ; 713.59,2601.26 J10.2@713.59,2625.98 ; 713.59,2650.7 J10.2@713.59,2625.98 ; 723.62,466.19 SS1.1@723.62,575.55 ; 723.62,684.91 SS1.1@723.62,575.55 ; 723.62,1922.88 SS3.1@723.62,2032.24 ; 723.62,2141.6 SS3.1@723.62,2032.24 ; 728.3,2802.57 J1.3@728.3,2860.78 ; 728.3,2918.98 J1.3@728.3,2860.78 ; 735.1,3146.28 J1.5@761.8,3146.28 ; 738.31,2625.98 J10.2@713.59,2625.98 ; 756.96,2860.78 J1.3@728.3,2860.78 ; 761.8,3092.03 J1.5@761.8,3146.28 ; 761.8,3200.53 J1.5@761.8,3146.28 ; 788.51,3146.28 J1.5@761.8,3146.28 ; 832.98,575.55 SS1.1@723.62,575.55 ; 832.98,2032.24 SS3.1@723.62,2032.24 ; 862.8,2639.41 J2.2@890.47,2639.41 ; 890.47,2611.73 J2.2@890.47,2639.41 ; 890.47,2667.08 J2.2@890.47,2639.41 ; 918.14,2639.41 J2.2@890.47,2639.41 ; 1048.7,319.64 J11.2@1091.14,319.64 ; 1091.14,277.21 J11.2@1091.14,319.64 ; 1091.14,362.08 J11.2@1091.14,319.64 ; 1133.58,319.64 J11.2@1091.14,319.64 ; 2372.42,2528.08 U25.17@2395.17,2528.08 2417.92,2528.08 ; 2372.42,2664.49 U25.11@2395.17,2664.49 2417.92,2664.49 ; 2372.42,2800.91 U25.5@2395.17,2800.91 2417.92,2800.91 ; 2411.79,2732.92 U25.8@2434.54,2732.92 2457.29,2732.92 ; 2411.79,2869.46 U25.2@2434.54,2869.46 ; 2434.54,2892.21 U25.2@2434.54,2869.46 ; 2457.29,2869.46 U25.2@2434.54,2869.46 ; 2623.17,2757.44 J17.16@2678.01,2757.44 ; 2727.24,104.49 J26.6@2755.9,104.49 ; 2755.9,75.83 J26.6@2755.9,104.49 ; 2755.9,133.14 J26.6@2755.9,104.49 ; 2784.56,104.49 J26.6@2755.9,104.49 ; 2818.98,575.55 SS2.1@2928.34,575.55 ; 2818.98,2032.24 SS4.1@2928.34,2032.24 ; 2928.34,466.19 SS2.1@2928.34,575.55 ; 2928.34,684.91 SS2.1@2928.34,575.55 ; 2928.34,1922.88 SS4.1@2928.34,2032.24 ; 2928.34,2141.6 SS4.1@2928.34,2032.24 ; 3037.7,575.55 SS2.1@2928.34,575.55 ; 3037.7,2032.24 SS4.1@2928.34,2032.24 ; 3199.68,104.49 J32.4@3228.34,104.49 ; 3228.34,75.83 J32.4@3228.34,104.49 ; 3228.34,133.14 J32.4@3228.34,104.49 ; 3257,104.49 J32.4@3228.34,104.49 ; 3283.47,375 J8.1@3320,375 ; J17.15@3287.85,2757.44 3342.69,2757.44 ; 3320,338.47 J8.1@3320,375 ; 3320,411.53 J8.1@3320,375 ; 3356.53,375 J8.1@3320,375 ; 3357.63,2704.29 J18.20@3427.62,2704.29 ; 3357.63,2927.91 J18.19@3427.62,2927.91 ; 3427.62,2634.3 J18.20@3427.62,2704.29 ; 3427.62,2774.28 J18.20@3427.62,2704.29 ; 3427.62,2857.92 J18.19@3427.62,2927.91 ; 3427.62,2997.9 J18.19@3427.62,2927.91 ; 3497.61,2704.29 J18.20@3427.62,2704.29 ; 3497.61,2927.91 J18.19@3427.62,2927.91 ; 3516.67,437.78 SS5.1@3626.03,437.78 ; 3519.83,2723.19 J18.13@3548.49,2723.19 ; 3519.83,2849.17 J18.4@3548.49,2849.17 ; 3548.49,2694.53 J18.13@3548.49,2723.19 ; 3548.49,2751.85 J18.13@3548.49,2723.19 ; 3548.49,2820.51 J18.4@3548.49,2849.17 ; 3548.49,2877.83 J18.4@3548.49,2849.17 ; 3577.15,2723.19 J18.13@3548.49,2723.19 ; 3577.15,2849.17 J18.4@3548.49,2849.17 ; 3626.03,328.42 SS5.1@3626.03,437.78 ; 3626.03,547.14 SS5.1@3626.03,437.78 ; 3657.62,2664.13 J18.16@3686.28,2664.13 ; 3657.62,2790.12 J18.7@3686.28,2790.12 ; 3672.12,104.49 J33.4@3700.78,104.49 ; 3686.28,2635.47 J18.16@3686.28,2664.13 ; 3686.28,2692.79 J18.16@3686.28,2664.13 ; 3686.28,2761.46 J18.7@3686.28,2790.12 ; 3686.28,2818.78 J18.7@3686.28,2790.12 ; 3700.78,75.83 J33.4@3700.78,104.49 ; 3700.78,133.14 J33.4@3700.78,104.49 ; 3714.94,2664.13 J18.16@3686.28,2664.13 ; 3714.94,2790.12 J18.7@3686.28,2790.12 ; 3729.44,104.49 J33.4@3700.78,104.49 ; 3735.39,437.78 SS5.1@3626.03,437.78 ; 3874.96,2704.29 J18.21@3944.95,2704.29 ; 3874.96,2927.91 J18.22@3944.95,2927.91 ; 3944.95,2634.3 J18.21@3944.95,2704.29 ; 3944.95,2774.28 J18.21@3944.95,2704.29 ; 3944.95,2857.92 J18.22@3944.95,2927.91 ; 3944.95,2997.9 J18.22@3944.95,2927.91 ; 4014.94,2704.29 J18.21@3944.95,2704.29 ; 4014.94,2927.91 J18.22@3944.95,2927.91 ; 4105.27,2657.04 J20.5@4177.23,2657.04 ; 4105.27,2885.39 J20.11@4177.23,2885.39 ; 4144.56,104.49 J34.4@4173.22,104.49 ; 4173.22,75.83 J34.4@4173.22,104.49 ; 4173.22,133.14 J34.4@4173.22,104.49 ; 4177.23,2585.08 J20.5@4177.23,2657.04 ; 4177.23,2729 J20.5@4177.23,2657.04 ; 4177.23,2813.43 J20.11@4177.23,2885.39 ; 4177.23,2957.35 J20.11@4177.23,2885.39 ; 4201.88,104.49 J34.4@4173.22,104.49 ; 4249.19,2657.04 J20.5@4177.23,2657.04 ; 4249.19,2885.39 J20.11@4177.23,2885.39 ; 4257.8,2657.04 J20.4@4297.3,2657.04 ; 4257.8,2775.15 J20.10@4297.3,2775.15 ; 4297.3,2617.54 J20.4@4297.3,2657.04 ; 4297.3,2696.54 J20.4@4297.3,2657.04 ; 4297.3,2735.65 J20.10@4297.3,2775.15 ; 4297.3,2814.65 J20.10@4297.3,2775.15 ; 4336.8,2657.04 J20.4@4297.3,2657.04 ; 4336.8,2775.15 J20.10@4297.3,2775.15 ; 4469.43,437.78 SS6.1@4578.79,437.78 ; 4578.79,328.42 SS6.1@4578.79,437.78 ; 4578.79,547.14 SS6.1@4578.79,437.78 ; 4617,104.49 J35.4@4645.66,104.49 ; 4621.01,2657.04 J20.6@4692.97,2657.04 ; 4621.01,2885.39 J20.12@4692.97,2885.39 ; 4645.66,75.83 J35.4@4645.66,104.49 ; 4645.66,133.14 J35.4@4645.66,104.49 ; 4674.32,104.49 J35.4@4645.66,104.49 ; 4688.15,437.78 SS6.1@4578.79,437.78 ; 4692.97,2585.08 J20.6@4692.97,2657.04 ; 4692.97,2729 J20.6@4692.97,2657.04 ; 4692.97,2813.43 J20.12@4692.97,2885.39 ; 4692.97,2957.35 J20.12@4692.97,2885.39 ; 4764.93,2657.04 J20.6@4692.97,2657.04 ; 4764.93,2885.39 J20.12@4692.97,2885.39
  BOTTOM w6: v1(2485,1590) 2505,1570 v1(2690,1570) 3075,1570 3130,1515 3450,1515 3645,1710 3645,1809.75 3698.93,1863.68 3740.55,1863.68 3764,1887.13 3764,1902.87 3751.87,1915 3730,1915 v1(3710,1895) 3685,1895 3605,1815 v1(3605,1725) 3435,1555 3150,1555 3080,1625 v1(3035,1625)
  BOTTOM w6.16: v1(2485,1590) 2507.44,1612.44 3022.44,1612.44 v1(3035,1625)
  BOTTOM w10: v1(30,1975) R6.2@90.32,1975 ; v1(30,2445) R22.2@85.32,2445 ; v1(78.52,1885) 88.84,1895.32 R8.2@200,1895.32 C18.1@240,1895.32 ; J9.4@120,766.54 161.86,724.68 D6.1@290,724.68 v1(290,755) ; C37.1@220,2365.32 226.18,2365.32 v1(240,2379.14) 253.82,2365.32 R25.2@260,2365.32 ; D5.1@290,564.68 v1(290,595) ; v1(379.41,465) U9.3@379.41,509.57 ; v1(379.41,625) U10.3@379.41,669.57 ; v1(405,1175) U7.2@405,1134.21 v1(405,1095) 484.68,1095 C44.2@500,1079.68 500,1085 539.68,1124.68 R33.2@539.68,1130 v1(569.68,1130) ; v1(480,495) C57.2@480,525.32 ; v1(480,658.52) C59.2@480,685.32 ; v1(575,1600) C9.2@575,1630.32 ; R29.2@659.68,1295 v1(659.68,1325) 659.68,1348.18 Q6.2@679,1367.5 ; v1(665,1600.32) R5.2@665,1630.32 ; R2.2@735,1289.68 v1(735,1325) ; v1(770.32,1100) C6.2@800.32,1100 ; v1(1000.32,2845) D30.1@1000.32,2875 ; v1(1119.68,2845) D31.1@1119.68,2875 ; C173.2@1379.68,2400 1379.68,2431.48 v1(1380,2431.8) ; C74.2@1590,1244.68 v1(1625,1244.68) ; v1(1630,1105) R78.2@1660.32,1105 ; R77.2@1749.68,1460 v1(1780,1460) ; v1(1800,1245) 1800.32,1244.68 U15.5@1800.32,1172.32 ; C73.2@1920,1244.68 v1(1950,1244.68) ; v1(1963.52,1105) R76.2@1990.32,1105 ; R75.2@2074.68,1460 v1(2105,1460) ; C53.2@2110,635.32 R35.2@2150,635.32 2200.32,635.32 2209.84,644.84 v1(2209.84,712.79) ; v1(2120,2330) D36.1@2120,2360.32 ; v1(2130,1245) 2130.32,1244.68 U14.5@2130.32,1172.32 ; v1(2150,2330) 2150,2350.32 D35.1@2160,2360.32 ; C84.2@2525,2080.32 2594.52,2080.32 v1(2623.23,2051.61) ; v1(2680,2330) D34.1@2680,2360.32 ; v1(3015,370) D50.1@3015,339.68 D49.1@3055,339.68 v1(3055,370) ; C87.2@3390,2054.68 3429.36,2015.32 R116.2@3430,2015.32 ; v1(4202.37,1665.47) 4216.9,1680 R203.2@4255.32,1680 ; v1(4643,1265) 4656.37,1265 4670,1278.63 U37.2@4670,1293.42 ; C64.2@4835,184.68 v1(4835,215) ; J12.13@4842.1,380.32 4842.1,431.78 v1(4845,434.68) ; C63.2@4875,184.68 v1(4875,215) ; v1(5070,1730) 5087.68,1747.68 J24.4@5135.46,1747.68 ; v1(5075,2682.01) 5076.26,2683.27 J23.18@5135.46,2683.27 ; v1(5075,2741.07) 5076.26,2742.32 J23.21@5135.46,2742.32 ; J23.4@5135.46,2407.68 v1(5180,2407.68) ; J12.12@5220.05,344.88 v1(5282.55,344.88)
  BOTTOM w12: C66.2@940,1295.32 C67.2@940,1244.68 v1(970,1244.68) ; U13.15@1044.8,1160.2 v1(1044.8,1215.2) ; C68.2@1309.68,1460 v1(1345,1460)
  BOTTOM w15: v1(235,840) C43.2@235,885.32 ; v1(235,1020) C46.2@235,1065.32 ; v1(235,1195) C40.2@235,1240.32 ; v1(290,840) C42.2@290,873.5 ; v1(290,1020) C45.2@290,1053.5 ; v1(290,1195) C39.2@290,1228.5 ; 375,3200 375,3146.28 J1.1@376,3146.28 ; U2.2@674.21,1755 v1(715,1755) 740,1730 C10.2@740,1723.5 751.82,1735.32 C11.2@790,1735.32 v1(790,1705) ; J1.5@761.8,3146.28 761.8,3200.84 ; v1(775,2315) 798.52,2315 808.52,2325 U12.4@832.05,2325 ; v1(995,2390) U24.2@1039.21,2390 ; v1(1180,2431.8) D45.1@1180,2460.32 ; v1(1250,2431.8) D46.1@1250,2460.32 ; v1(1380,2431.8) D42.1@1380,2460.32 ; v1(1435,2431.8) R216.2@1435,2460.32 ; v1(1475,2431.8) D43.1@1475,2460.32 ; v1(2115,2570) U27.3@2144.25,2570 U27.8@2175.75,2570 v1(2205,2570) ; v1(2115,2710) U26.3@2144.25,2710 U26.8@2175.75,2710 v1(2205,2710) ; v1(2160,2955) R218.2@2160,2995.32 ; v1(2395,2196.22) D33.1@2395,2240.32 R154.2@2435,2240.32 v1(2435,2196.22) ; v1(2515,2196.22) D37.1@2515,2240.32 C129.2@2555,2240.32 v1(2555,2196.22) ; R114.2@2960,3069.68 v1(2960,3115) ; v1(2968.2,2250) 2977.88,2240.32 C92.2@2995,2240.32 ; R115.2@3000,3069.68 v1(3000,3115) ; C89.2@3095,2279.68 3119.68,2279.68 3135,2295 v1(3136.56,2295) ; v1(3490,2105) 3510,2085 R121.1@3510,2054.68 ; v1(3635,2435) U18.3@3635,2464.25 U18.8@3635,2495.75 v1(3635,2545) ; C168.2@3640,2150.32 3640,2134.34 v1(3669.34,2105) ; v1(3770,2435) U19.3@3770,2464.25 U19.8@3770,2495.75 v1(3770,2545.25) ; C167.2@3870,2345.32 v1(3904.68,2345.32) ; v1(4047.3,2225) 4080,2192.3 C169.2@4080,2189.68 ; v1(4240,2435) U20.3@4240,2464.25 U20.8@4240,2495.75 v1(4240,2521.57) ; v1(4510,775) C71.2@4540.32,775 ; v1(4513.52,1240) C164.2@4540.32,1240 ; v1(4513.52,1360) C162.2@4540.32,1360 ; v1(4513.52,1400) C163.2@4540.32,1400 ; v1(4615,630) D15.1@4645.32,630 ; v1(4615,675) D16.1@4645.32,675 ; v1(4615,720) D17.1@4645.32,720 ; v1(4615,775) C72.2@4645.32,775 ; v1(4615,830) D18.1@4645.32,830 ; v1(4615,875) D19.1@4645.32,875 ; v1(4615,920) D20.1@4645.32,920 ; v1(4615,965) D21.1@4645.32,965 ; v1(4643,1228) v1(4643,1265) ; v1(4673,1640) 4678,1635 R187.2@4700.32,1635 C143.2@4700.32,1675 ; U36.5@4821.24,1220.16 4849.84,1220.16 v1(4865,1205) ; v1(4915,60) C62.2@4915,145.32
  BOTTOM w20: v1(875,2795.32) R150.2@905,2795.32 ; J34.4@4173.22,104.49 4239.49,104.49 4258.5,123.5 C75.2@4258.5,225 ; v1(4760,801.48) 4783.53,777.95 J12.6@4822.41,777.95
  BOTTOM w25: 70.08,1011.58 J3.6@98.74,1011.58 ; 84.45,766.54 J9.4@120,766.54 ; 98.74,982.92 J3.6@98.74,1011.58 ; 98.74,1040.23 J3.6@98.74,1011.58 ; 120,731 J9.4@120,766.54 ; 120,802.09 J9.4@120,766.54 ; 127.4,1011.58 J3.6@98.74,1011.58 ; 155.55,766.54 J9.4@120,766.54 ; 376,3092.03 J1.1@376,3146.28 402.7,3146.28 ; 491.05,2860.78 J1.2@519.7,2860.78 ; 519.7,2918.98 J1.2@519.7,2860.78 ; 548.35,2860.78 J1.2@519.7,2860.78 ; 598.71,319.64 J11.5@641.14,319.64 ; 641.14,277.21 J11.5@641.14,319.64 ; 683.58,319.64 J11.5@641.14,319.64 ; 699.65,2860.78 J1.3@728.3,2860.78 ; 728.3,2802.57 J1.3@728.3,2860.78 ; 728.3,2918.98 J1.3@728.3,2860.78 ; 735.1,3146.28 J1.5@761.8,3146.28 ; 756.96,2860.78 J1.3@728.3,2860.78 ; 761.8,3092.03 J1.5@761.8,3146.28 ; 788.51,3146.28 J1.5@761.8,3146.28 ; 890.47,2611.73 J2.2@890.47,2639.41 890.47,2667.08 ; 1048.7,319.64 J11.2@1091.14,319.64 ; 1091.14,277.21 J11.2@1091.14,319.64 ; 1133.58,319.64 J11.2@1091.14,319.64 ; 2727.24,104.49 J26.6@2755.9,104.49 ; 2755.9,75.83 J26.6@2755.9,104.49 ; 2755.9,133.14 J26.6@2755.9,104.49 ; 2784.56,104.49 J26.6@2755.9,104.49 ; 2928.34,466.19 SS2.1@2928.34,575.55 3037.7,575.55 ; 3199.68,104.49 J32.4@3228.34,104.49 ; 3228.34,75.83 J32.4@3228.34,104.49 ; 3228.34,133.14 J32.4@3228.34,104.49 ; 3257,104.49 J32.4@3228.34,104.49 ; 3283.47,375 J8.1@3320,375 ; 3320,338.47 J8.1@3320,375 ; 3320,411.53 J8.1@3320,375 ; 3356.53,375 J8.1@3320,375 ; 3516.67,437.78 SS5.1@3626.03,437.78 ; 3626.03,328.42 SS5.1@3626.03,437.78 ; 3626.03,547.14 SS5.1@3626.03,437.78 ; 3672.12,104.49 J33.4@3700.78,104.49 ; 3700.78,75.83 J33.4@3700.78,104.49 ; 3700.78,133.14 J33.4@3700.78,104.49 ; 3729.44,104.49 J33.4@3700.78,104.49 ; 3735.39,437.78 SS5.1@3626.03,437.78 ; 4144.56,104.49 J34.4@4173.22,104.49 ; 4173.22,75.83 J34.4@4173.22,104.49 ; 4173.22,133.14 J34.4@4173.22,104.49 ; 4469.43,437.78 SS6.1@4578.79,437.78 ; 4578.79,328.42 SS6.1@4578.79,437.78 ; 4578.79,547.14 SS6.1@4578.79,437.78 ; 4617,104.49 J35.4@4645.66,104.49 ; 4621.01,2885.39 J20.12@4692.97,2885.39 ; 4645.66,75.83 J35.4@4645.66,104.49 ; 4645.66,133.14 J35.4@4645.66,104.49 ; 4674.32,104.49 J35.4@4645.66,104.49 ; 4688.15,437.78 SS6.1@4578.79,437.78 ; 4692.97,2813.43 J20.12@4692.97,2885.39 ; 4692.97,2957.35 J20.12@4692.97,2885.39 ; 4764.93,2885.39 J20.12@4692.97,2885.39 ; 4831.17,1024.09 U36.9@4879.51,1024.09 ; 4842.1,985.74 J12.10@4842.1,955.12 4884.1,955.12 ; 4879.51,997.41 U36.9@4879.51,1024.09 ; 4879.51,1050.78 U36.9@4879.51,1024.09 ; 4879.51,1509.22 U36.8@4879.51,1535.9 4927.85,1535.9 ; 4927.85,1024.09 U36.9@4879.51,1024.09 ; 5165.55,955.12 J12.11@5220.05,955.12 ; 5195.47,2208.31 J24.25@5241.84,2208.31 ; 5195.47,2281.7 J23.26@5241.84,2281.7 ; 5195.47,2868.31 J23.25@5241.84,2868.31 ; 5220.05,918.12 J12.11@5220.05,955.12 ; 5220.05,992.12 J12.11@5220.05,955.12 ; 5241.84,1583.2 J24.26@5241.84,1621.69 ; 5241.84,1660.19 J24.26@5241.84,1621.69 ; 5241.84,2169.81 J24.25@5241.84,2208.31 ; 5241.84,2320.19 J23.26@5241.84,2281.7 ; 5241.84,2829.81 J23.25@5241.84,2868.31 ; 5241.84,2906.8 J23.25@5241.84,2868.31 ; 5274.55,955.12 J12.11@5220.05,955.12 ; 5288.21,1621.69 J24.26@5241.84,1621.69 ; 5288.21,2208.31 J24.25@5241.84,2208.31 ; 5288.21,2281.7 J23.26@5241.84,2281.7 ; v1@5288.21,2868.31 J23.25@5241.84,2868.31 ; v1@5303.61,1024.09 U36.11@5351.95,1024.09 ; v1@5303.61,1535.9 U36.10@5351.95,1535.9 ; 5351.95,997.41 U36.11@5351.95,1024.09 ; 5351.95,1050.78 U36.11@5351.95,1024.09 ; 5351.95,1509.22 U36.10@5351.95,1535.9 ; 5351.95,1562.59 U36.10@5351.95,1535.9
